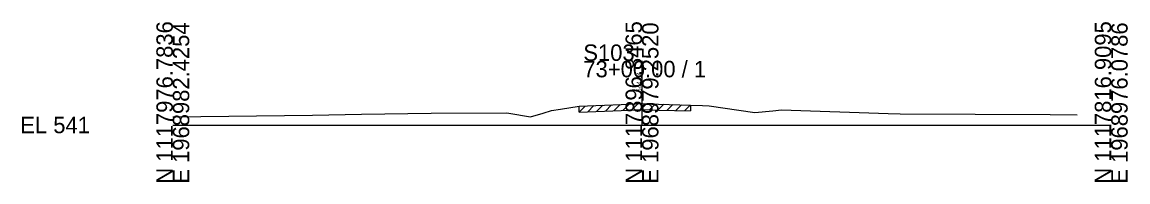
# Model space of a CAD drawing. Extents: x -26 to 163, y -10 to 45020.
# Drawn here: x -25.7 to 162.8, y 31990.3 to 32017.5 of the extents above; entities that cross this region are included whole.
import ezdxf

# ---------------------------------------------------------------- set-up
doc = ezdxf.new("R2010")
doc.units = 0
for name, color, linetype in [('RD_GPK_XS_Cell', 7, 'Continuous'), ('RD_XS_ExGround', 7, 'Continuous'), ('RD_XS_ExPaveRet', 7, 'Continuous'), ('RD_XS_TX_Elev_EX', 7, 'Continuous')]:
    doc.layers.add(name, color=color, linetype=linetype)

msp = doc.modelspace()

# ---------------------------------------------------------------- linework, layer by layer
at = {"layer": 'RD_GPK_XS_Cell'}
for p, q in [((80, 32000), (80, 32010.93)), ((0, 32000), (80, 32000)), ((80, 32000), (160, 32000))]:
    msp.add_line(p, q, dxfattribs=at)
at = {"layer": 'RD_XS_ExGround'}
for p, q in [((69.26, 32003.19), (76.42, 32003.49)), ((76.42, 32003.49), (80.06, 32003.64)), ((80.06, 32003.64), (82.83, 32003.55)), ((82.83, 32003.55), (88.27, 32003.39)), ((0, 32001.37), (23.84, 32001.68)), ((23.84, 32001.68), (32.19, 32001.85)), ((32.19, 32001.85), (44.07, 32002)), ((44.07, 32002), (56.87, 32002.06)), ((56.87, 32002.06), (57.32, 32001.99)), ((57.32, 32001.99), (61.01, 32001.38)), ((61.01, 32001.38), (63.14, 32002.03)), ((63.14, 32002.03), (64.57, 32002.45)), ((64.57, 32002.45), (66.11, 32002.69)), ((66.11, 32002.69), (69.26, 32003.19)), ((88.27, 32003.39), (90.33, 32003.32)), ((90.33, 32003.32), (91.43, 32003.27)), ((91.43, 32003.27), (96.53, 32002.53)), ((96.53, 32002.53), (99.25, 32002.13)), ((99.25, 32002.13), (102.29, 32002.44)), ((102.29, 32002.44), (103.8, 32002.6)), ((103.8, 32002.6), (121.99, 32001.98)), ((121.99, 32001.98), (124.04, 32001.92)), ((124.04, 32001.92), (149.6, 32001.8)), ((149.6, 32001.8), (154.17, 32001.73))]:
    msp.add_line(p, q, dxfattribs=at)
at = {"layer": 'RD_XS_ExPaveRet'}
for p, q in [((73.76, 32002.38), (74.8, 32003.43)), ((75.26, 32002.45), (76.3, 32003.49)), ((76.76, 32002.51), (77.8, 32003.55)), ((78.26, 32002.57), (79.3, 32003.61)), ((79.76, 32002.63), (80.75, 32003.62)), ((81.26, 32002.61), (82.23, 32003.57)), ((82.76, 32002.56), (83.73, 32003.53)), ((84.26, 32002.51), (85.23, 32003.48)), ((85.76, 32002.46), (86.73, 32003.43)), ((69.26, 32002.19), (70.3, 32003.23)), ((69.26, 32002.19), (69.26, 32003.19)), ((69.26, 32002.19), (76.42, 32002.49)), ((70.76, 32002.25), (71.8, 32003.3)), ((72.26, 32002.32), (73.3, 32003.36)), ((76.42, 32002.49), (80.06, 32002.64)), ((80.06, 32002.64), (82.83, 32002.55)), ((82.83, 32002.55), (88.27, 32002.39)), ((87.26, 32002.42), (88.23, 32003.39)), ((88.27, 32003.39), (88.27, 32002.39))]:
    msp.add_line(p, q, dxfattribs=at)

# ---------------------------------------------------------------- texts
at = {"layer": 'RD_GPK_XS_Cell'}
for s, p in [('N 1117976.7836', (0, 31990)), ('E 1968982.4254', (2.8, 31990)), ('N 1117896.8465', (80, 31990)), ('E 1968979.2520', (82.8, 31990)), ('N 1117816.9095', (160, 31990)), ('E 1968976.0786', (162.8, 31990))]:
    msp.add_text(s, height=2.8, rotation=90, dxfattribs=at).set_placement(p)
for s, p in [('S103', (70, 32010.93)), ('73+00.00 / 1', (70, 32008.13)), ('EL 541', (-26, 31998.6))]:
    msp.add_text(s, height=2.8, dxfattribs=at).set_placement(p)
at = {"layer": 'RD_XS_TX_Elev_EX'}
msp.add_text('544.64', height=0.8, rotation=90, dxfattribs=at).set_placement((79.9, 32005.64))

doc.saveas('drawing.dxf')
